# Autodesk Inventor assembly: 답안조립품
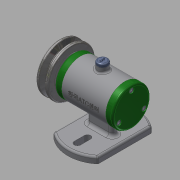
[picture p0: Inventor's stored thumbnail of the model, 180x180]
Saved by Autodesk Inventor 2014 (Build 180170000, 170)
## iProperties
Created: 2017-12
Part Number: 답안조립품
Document SubType Name: Assembly
Designer: user
Author: user
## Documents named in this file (14)
- C:\Users\user\Desktop\471208V1004\답안조립품.iam
- C:\Users\user\Desktop\471208V1004\본체.ipt
- C:\Users\user\Desktop\471208V1004\앞커버.ipt
- C:\Users\user\Desktop\471208V1004\베어링 15 x 32 x 9.ipt
- C:\Users\user\Desktop\471208V1004\뒤커버.ipt
- C:\Users\user\Desktop\471208V1004\고무캡.ipt
- C:\Users\user\Desktop\471208V1004\축.ipt
- C:\Users\user\Desktop\471208V1004\키 3 x 3 x 12.ipt
- C:\Users\user\Desktop\471208V1004\V벨트풀리.ipt
- C:\Users\user\Desktop\471208V1004\와셔 8x17.ipt
- C:\Users\user\Desktop\471208V1004\스프링와셔 8.ipt
- C:\Users\user\Desktop\471208V1004\너트 M 8.ipt
- C:\Users\user\Desktop\471208V1004\볼트 M4 x 12.ipt
- C:\Users\user\Desktop\471208V1004\오일 실 15 25 7.ipt
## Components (2 placed, 2 different names)
1. 고무캡:1
2. V벨트풀리:1 — 각도:1
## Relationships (1: Angle 1)
- 각도:1 [Angle]: V벨트풀리:1
